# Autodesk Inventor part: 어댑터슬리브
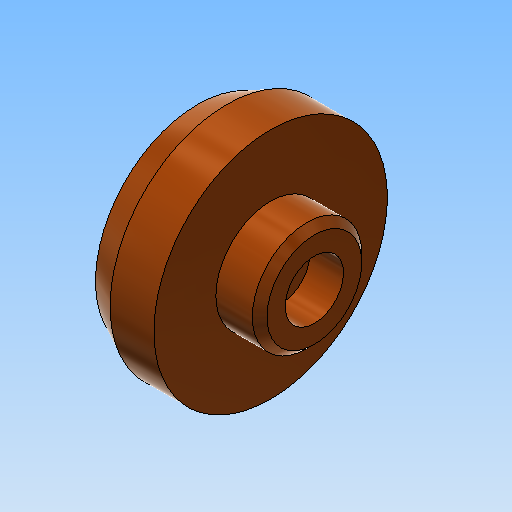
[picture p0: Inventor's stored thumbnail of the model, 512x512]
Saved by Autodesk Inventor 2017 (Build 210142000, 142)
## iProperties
Created: 2016-06
Part Number: 어댑터슬리브
Material: 강철, 탄소
Document SubType Name: Modeling
Designer: mduedu
Density: 7.87 g/cm^3
Appearance: 매끄러움 - 연한 주황색
Author: mduedu
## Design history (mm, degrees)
sketch "스케치2"
  geometry: L1 (0, 0)-(0, 14); L2 (0, 14)-(-4, 16); L3 (-4, 16)-(-10, 16); L4 (-10, 16)-(-10, 7.5); L5 (-10, 7.5)-(-16, 7.5); L6 (-16, 7.5)-(-16, 0); L7 (-16, 0)-(0, 0)
  constraints: 14 end point, 4 parallel, 1 perpendicular, 1 vertical
  dimensions: "d0" = 32 diameter of L3 L7; "d2" = 28 diameter of L1.end L7; "d3" = 6 distance of L2.end L3.end; "d4" = 6 distance of L4.end L5.end; "d5" = 15 diameter of L5 L7; "d6" = 16 distance between parallel lines of L6 L1
revolve "회전1" sketch "스케치2" stored, may be unused: angle "d7" = 90 deg
sketch "스케치3"
  geometry: L1 (-16, -7.5)-(-16, 7.5) reference; L2 (-16, 7.5)-(-10, 7.5) reference; L3 (-10, 7.5)-(-10, 16) reference; L4 (-10, 16)-(-4, 16) reference; L5 (-4, 16)-(0, 14) reference; L6 (0, 14)-(0, -14) reference; L7 (0, -14)-(-4, -16) reference; L8 (-4, -16)-(-10, -16) reference; L9 (-10, -16)-(-10, -7.5) reference; L10 (-10, -7.5)-(-16, -7.5) reference; L11 (0, 10)-(-5, 10); L12 (-5, 10)-(-5, 8); L13 (-5, 8)-(-7, 6); L14 (-7, 6)-(-7, 0); L15 (-7, 0)-(0, 0); L16 (0, 10)-(0, 0)
  constraints: 12 end point, 3 parallel, 2 perpendicular, 1 point on line
  dimensions: "d8" = 20 diameter of L11 L15; "d10" = 16 diameter of L12.end L15; "d11" = 12 diameter of L13.end L15; "d12" = 9 distance between parallel lines of L14 L1; "d13" = 2 distance between parallel lines of L12 L14
revolve "회전2" sketch "스케치3" stored, may be unused: angle "d14" = 90 deg
chamfer "모따기1" distance "d15" = 1; stored, may be unused: second distance "d16" = 2, angle "d17" = 45 deg
sketch "스케치4"
  geometry: 2 further points
  constraints: 1 coincident
sketch "스케치5"
  geometry: 1 further point
hole "구멍1" sketch "스케치5" at (0, 0) diameter "d18" = 4.5; stored, may be unused: countersink angle "d22" = 90 deg, drill point angle "d24" = 0 deg; dims "d19" = 6, "d20" = 8, "d21" = 4.6, "d23" = 8
node "솔리드1"
node "절단 모서리 투영1"
